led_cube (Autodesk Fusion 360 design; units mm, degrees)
part number: 2026-10-16-17-34-12-747
parameter "cube" = 60 comment "job b4419e02"
parameter "wall" = 2.4 comment "job b4419e02"
parameter "lidT" = 2.4 comment "job b4419e02"
parameter "clr" = 0.2 comment "job b4419e02"
parameter "pcb" = 50 comment "job b4419e02"
parameter "pcbT" = 1.6 comment "job b4419e02"
parameter "pocket" = 50.4 comment "job b4419e02"
parameter "rimW" = 1.8 comment "job b4419e02"
parameter "standoff" = 5 comment "job b4419e02"
parameter "ledH" = 1.6 comment "job b4419e02"
parameter "ledGap" = 15 comment "job b4419e02"
parameter "hookLap" = 0.5 comment "job b4419e02"
parameter "acrT" = 2 comment "job b4419e02"
parameter "acrW" = 56 comment "job b4419e02"
parameter "acrH" = 57 comment "job b4419e02"
parameter "slotW" = 2.3 comment "job b4419e02"
parameter "slotD" = 1.5 comment "job b4419e02"
parameter "win" = 52 comment "job b4419e02"
parameter "cableD" = 5 comment "job b4419e02"
parameter "skirtT" = 1.6 comment "job b4419e02"
parameter "skirtH" = 4 comment "job b4419e02"
parameter "snapL" = 8 comment "job b4419e02"
parameter "snapP" = 0.5 comment "job b4419e02"
parameter "snapH" = 1 comment "job b4419e02"
work_plane "WorkPlane1" AlongDistance 0 ExtraOffset 0
sketch "TubOuter" plane through (0, 0, 0) normal (0, 0, 1) x axis (1, 0, 0)
  line L1 (30, -30) -> (-30, -30)
  line L2 (30, 30) -> (30, -30)
  line L3 (-30, 30) -> (30, 30)
  line L4 (-30, -30) -> (-30, 30)
extrude "Extrude1" new body sketch "TubOuter" along normal blind 57.6 bodies "Tub"
work_plane "WorkPlane2" AlongDistance 2.4 ExtraOffset 0
sketch "Cavity" plane through (0, 0, 2.4) normal (0, 0, 1) x axis (1, 0, 0)
  line L1 (27.6, -27.6) -> (-27.6, -27.6)
  line L2 (27.6, 27.6) -> (27.6, -27.6)
  line L3 (-27.6, 27.6) -> (27.6, 27.6)
  line L4 (-27.6, -27.6) -> (-27.6, 27.6)
extrude "Extrude2" cut sketch "Cavity" along normal blind 55.2
work_plane "WorkPlane3" AlongDistance 4 ExtraOffset 0
sketch "FrontWindow" plane through (0, 0, 4) normal (0, 0, 1) x axis (1, 0, 0)
  line L1 (26, -30) -> (-26, -30)
  line L2 (26, -27.6) -> (26, -30)
  line L3 (-26, -27.6) -> (26, -27.6)
  line L4 (-26, -30) -> (-26, -27.6)
extrude "Extrude3" cut sketch "FrontWindow" along normal blind 52
work_plane "WorkPlane4" AlongDistance 0.9 ExtraOffset 0
sketch "DiffuserSlot" plane through (0, 0, 0.9) normal (0, 0, 1) x axis (1, 0, 0)
  line L1 (29.1, -27.6) -> (-29.1, -27.6)
  line L2 (29.1, -25.3) -> (29.1, -27.6)
  line L3 (-29.1, -25.3) -> (29.1, -25.3)
  line L4 (-29.1, -27.6) -> (-29.1, -25.3)
extrude "Extrude4" cut sketch "DiffuserSlot" along normal blind 56.7
sketch "Bulkhead" plane through (0, 0, 2.4) normal (0, 0, 1) x axis (1, 0, 0)
  line L1 (27.6, -2.4) -> (-27.6, -2.4)
  line L2 (27.6, 0) -> (27.6, -2.4)
  line L3 (-27.6, 0) -> (27.6, 0)
  line L4 (-27.6, -2.4) -> (-27.6, 0)
extrude "Extrude5" add sketch "Bulkhead" along normal blind 51
work_plane "WorkPlane5" AlongDistance 6 ExtraOffset 0
sketch "BulkheadCableHole" plane through (0, 0, 6) normal (0, 0, 1) x axis (1, 0, 0)
  line L1 (5, -2.4) -> (-5, -2.4)
  line L2 (5, 0) -> (5, -2.4)
  line L3 (-5, 0) -> (5, 0)
  line L4 (-5, -2.4) -> (-5, 0)
extrude "Extrude6" cut sketch "BulkheadCableHole" along normal blind 6
work_plane "WorkPlane6" AlongDistance 3 ExtraOffset 0
sketch "PocketRim" plane through (0, 0, 3) normal (0, 0, 1) x axis (1, 0, 0)
  line L1 (27, -9) -> (-27, -9)
  line L2 (27, -2.4) -> (27, -9)
  line L3 (-27, -2.4) -> (27, -2.4)
  line L4 (-27, -9) -> (-27, -2.4)
extrude "Extrude7" add sketch "PocketRim" along normal blind 54
work_plane "WorkPlane7" AlongDistance 4.8 ExtraOffset 0
sketch "PocketInner" plane through (0, 0, 4.8) normal (0, 0, 1) x axis (1, 0, 0)
  line L1 (25.2, -9) -> (-25.2, -9)
  line L2 (25.2, -2.4) -> (25.2, -9)
  line L3 (-25.2, -2.4) -> (25.2, -2.4)
  line L4 (-25.2, -9) -> (-25.2, -2.4)
extrude "Extrude8" cut sketch "PocketInner" along normal blind 50.4
work_plane "WorkPlane8" AlongDistance 5 ExtraOffset 0
sketch "Standoff0" plane through (0, 0, 5) normal (0, 0, 1) x axis (1, 0, 0)
  line L1 (-20, -7.4) -> (-25, -7.4)
  line L2 (-20, -2.4) -> (-20, -7.4)
  line L3 (-25, -2.4) -> (-20, -2.4)
  line L4 (-25, -7.4) -> (-25, -2.4)
extrude "Extrude9" add sketch "Standoff0" along normal blind 5
sketch "Standoff1" plane through (0, 0, 5) normal (0, 0, 1) x axis (1, 0, 0)
  line L1 (25, -7.4) -> (20, -7.4)
  line L2 (25, -2.4) -> (25, -7.4)
  line L3 (20, -2.4) -> (25, -2.4)
  line L4 (20, -7.4) -> (20, -2.4)
extrude "Extrude10" add sketch "Standoff1" along normal blind 5
work_plane "WorkPlane9" AlongDistance 50 ExtraOffset 0
sketch "Standoff2" plane through (0, 0, 50) normal (0, 0, 1) x axis (1, 0, 0)
  line L1 (-20, -7.4) -> (-25, -7.4)
  line L2 (-20, -2.4) -> (-20, -7.4)
  line L3 (-25, -2.4) -> (-20, -2.4)
  line L4 (-25, -7.4) -> (-25, -2.4)
extrude "Extrude11" add sketch "Standoff2" along normal blind 5
sketch "Standoff3" plane through (0, 0, 50) normal (0, 0, 1) x axis (1, 0, 0)
  line L1 (25, -7.4) -> (20, -7.4)
  line L2 (25, -2.4) -> (25, -7.4)
  line L3 (20, -2.4) -> (25, -2.4)
  line L4 (20, -7.4) -> (20, -2.4)
extrude "Extrude12" add sketch "Standoff3" along normal blind 5
work_plane "WorkPlane10" AlongDistance 54.5 ExtraOffset 0
sketch "HookTop" plane through (0, 0, 54.5) normal (0, 0, 1) x axis (1, 0, 0)
  line L1 (4, -9.8) -> (-4, -9.8)
  line L2 (4, -9) -> (4, -9.8)
  line L3 (-4, -9) -> (4, -9)
  line L4 (-4, -9.8) -> (-4, -9)
extrude "Extrude13" add sketch "HookTop" along normal blind 2.5
sketch "HookBottom" plane through (0, 0, 3) normal (0, 0, 1) x axis (1, 0, 0)
  line L1 (4, -9.8) -> (-4, -9.8)
  line L2 (4, -9) -> (4, -9.8)
  line L3 (-4, -9) -> (4, -9)
  line L4 (-4, -9.8) -> (-4, -9)
extrude "Extrude14" add sketch "HookBottom" along normal blind 2.5
sketch "HookReliefL" plane through (0, 0, 3) normal (0, 0, 1) x axis (1, 0, 0)
  line L1 (-4, -9) -> (-5, -9)
  line L2 (-4, -2.4) -> (-4, -9)
  line L3 (-5, -2.4) -> (-4, -2.4)
  line L4 (-5, -9) -> (-5, -2.4)
extrude "Extrude15" cut sketch "HookReliefL" along normal blind 1.8
sketch "HookReliefR" plane through (0, 0, 3) normal (0, 0, 1) x axis (1, 0, 0)
  line L1 (5, -9) -> (4, -9)
  line L2 (5, -2.4) -> (5, -9)
  line L3 (4, -2.4) -> (5, -2.4)
  line L4 (4, -9) -> (4, -2.4)
extrude "Extrude16" cut sketch "HookReliefR" along normal blind 1.8
sketch "ReliefPin0" plane through (0, 0, 2.4) normal (0, 0, 1) x axis (1, 0, 0)
  line L1 (-2, 20) -> (-6, 20)
  line L2 (-2, 24) -> (-2, 20)
  line L3 (-6, 24) -> (-2, 24)
  line L4 (-6, 20) -> (-6, 24)
extrude "Extrude17" add sketch "ReliefPin0" along normal blind 6
sketch "ReliefPin1" plane through (0, 0, 2.4) normal (0, 0, 1) x axis (1, 0, 0)
  line L1 (6, 13) -> (2, 13)
  line L2 (6, 17) -> (6, 13)
  line L3 (2, 17) -> (6, 17)
  line L4 (2, 13) -> (2, 17)
extrude "Extrude18" add sketch "ReliefPin1" along normal blind 6
sketch "ReliefPin2" plane through (0, 0, 2.4) normal (0, 0, 1) x axis (1, 0, 0)
  line L1 (-2, 6) -> (-6, 6)
  line L2 (-2, 10) -> (-2, 6)
  line L3 (-6, 10) -> (-2, 10)
  line L4 (-6, 6) -> (-6, 10)
extrude "Extrude19" add sketch "ReliefPin2" along normal blind 6
sketch "CableGrommet" plane through (0, 30, 0) normal (0, 1, 0) x axis (-1, 0, 0)
  line L1 (30, 0) -> (-30, 0)
  line L2 (30, 57.6) -> (30, 0)
  line L3 (-30, 57.6) -> (30, 57.6)
  line L4 (-30, 0) -> (-30, 57.6)
  circle C1 centre (0, 5.9) radius 2.5
extrude "Extrude20" cut sketch "CableGrommet" profile of C1 against normal blind 2.9
work_plane "WorkPlane11" AlongDistance 57.6 ExtraOffset 0
sketch "LidPlate" plane through (0, 0, 57.6) normal (0, 0, 1) x axis (1, 0, 0)
  line L1 (30, -30) -> (-30, -30)
  line L2 (30, 30) -> (30, -30)
  line L3 (-30, 30) -> (30, 30)
  line L4 (-30, -30) -> (-30, 30)
extrude "Extrude21" new body sketch "LidPlate" along normal blind 2.4 bodies "Lid"
work_plane "WorkPlane12" AlongDistance 53.6 ExtraOffset 0
sketch "Skirt" plane through (0, 0, 53.6) normal (0, 0, 1) x axis (1, 0, 0)
  line L1 (27.4, -25.1) -> (-27.4, -25.1)
  line L2 (27.4, 27.4) -> (27.4, -25.1)
  line L3 (-27.4, 27.4) -> (27.4, 27.4)
  line L4 (-27.4, -25.1) -> (-27.4, 27.4)
extrude "Extrude22" add sketch "Skirt" along normal blind 4
sketch "SkirtInner" plane through (0, 0, 53.6) normal (0, 0, 1) x axis (1, 0, 0)
  line L1 (25.8, -23.5) -> (-25.8, -23.5)
  line L2 (25.8, 25.8) -> (25.8, -23.5)
  line L3 (-25.8, 25.8) -> (25.8, 25.8)
  line L4 (-25.8, -23.5) -> (-25.8, 25.8)
extrude "Extrude23" cut sketch "SkirtInner" along normal blind 4
sketch "SkirtNotch" plane through (0, 0, 53.6) normal (0, 0, 1) x axis (1, 0, 0)
  line L1 (27.5, -9.4) -> (-27.5, -9.4)
  line L2 (27.5, -2) -> (27.5, -9.4)
  line L3 (-27.5, -2) -> (27.5, -2)
  line L4 (-27.5, -9.4) -> (-27.5, -2)
extrude "Extrude24" cut sketch "SkirtNotch" along normal blind 4
sketch "LidDiffuserGroove" plane through (0, 0, 57.6) normal (0, 0, 1) x axis (1, 0, 0)
  line L1 (29.1, -27.6) -> (-29.1, -27.6)
  line L2 (29.1, -25.3) -> (29.1, -27.6)
  line L3 (-29.1, -25.3) -> (29.1, -25.3)
  line L4 (-29.1, -27.6) -> (-29.1, -25.3)
extrude "Extrude25" cut sketch "LidDiffuserGroove" along normal blind 1.5
work_plane "WorkPlane13" AlongDistance 55.1 ExtraOffset 0
sketch "SnapBumpL" plane through (0, 0, 55.1) normal (0, 0, 1) x axis (1, 0, 0)
  line L1 (-27.4, 8) -> (-27.9, 8)
  line L2 (-27.4, 16) -> (-27.4, 8)
  line L3 (-27.9, 16) -> (-27.4, 16)
  line L4 (-27.9, 8) -> (-27.9, 16)
extrude "Extrude26" add sketch "SnapBumpL" along normal blind 1
work_plane "WorkPlane14" AlongDistance 54.9 ExtraOffset 0
sketch "SnapGrooveL" plane through (0, 0, 54.9) normal (0, 0, 1) x axis (1, 0, 0)
  line L1 (-27.6, 7.8) -> (-28.5, 7.8)
  line L2 (-27.6, 16.2) -> (-27.6, 7.8)
  line L3 (-28.5, 16.2) -> (-27.6, 16.2)
  line L4 (-28.5, 7.8) -> (-28.5, 16.2)
extrude "Extrude27" cut sketch "SnapGrooveL" along normal blind 1.4
sketch "SnapBumpR" plane through (0, 0, 55.1) normal (0, 0, 1) x axis (1, 0, 0)
  line L1 (27.9, 8) -> (27.4, 8)
  line L2 (27.9, 16) -> (27.9, 8)
  line L3 (27.4, 16) -> (27.9, 16)
  line L4 (27.4, 8) -> (27.4, 16)
extrude "Extrude28" add sketch "SnapBumpR" along normal blind 1
sketch "SnapGrooveR" plane through (0, 0, 54.9) normal (0, 0, 1) x axis (1, 0, 0)
  line L1 (28.5, 7.8) -> (27.6, 7.8)
  line L2 (28.5, 16.2) -> (28.5, 7.8)
  line L3 (27.6, 16.2) -> (28.5, 16.2)
  line L4 (27.6, 7.8) -> (27.6, 16.2)
extrude "Extrude29" cut sketch "SnapGrooveR" along normal blind 1.4
sketch "SnapBumpBL" plane through (0, 0, 55.1) normal (0, 0, 1) x axis (1, 0, 0)
  line L1 (-8, 27.4) -> (-16, 27.4)
  line L2 (-8, 27.9) -> (-8, 27.4)
  line L3 (-16, 27.9) -> (-8, 27.9)
  line L4 (-16, 27.4) -> (-16, 27.9)
extrude "Extrude30" add sketch "SnapBumpBL" along normal blind 1
sketch "SnapGrooveBL" plane through (0, 0, 54.9) normal (0, 0, 1) x axis (1, 0, 0)
  line L1 (-7.8, 27.6) -> (-16.2, 27.6)
  line L2 (-7.8, 28.5) -> (-7.8, 27.6)
  line L3 (-16.2, 28.5) -> (-7.8, 28.5)
  line L4 (-16.2, 27.6) -> (-16.2, 28.5)
extrude "Extrude31" cut sketch "SnapGrooveBL" along normal blind 1.4
sketch "SnapBumpBR" plane through (0, 0, 55.1) normal (0, 0, 1) x axis (1, 0, 0)
  line L1 (16, 27.4) -> (8, 27.4)
  line L2 (16, 27.9) -> (16, 27.4)
  line L3 (8, 27.9) -> (16, 27.9)
  line L4 (8, 27.4) -> (8, 27.9)
extrude "Extrude32" add sketch "SnapBumpBR" along normal blind 1
sketch "SnapGrooveBR" plane through (0, 0, 54.9) normal (0, 0, 1) x axis (1, 0, 0)
  line L1 (16.2, 27.6) -> (7.8, 27.6)
  line L2 (16.2, 28.5) -> (16.2, 27.6)
  line L3 (7.8, 28.5) -> (16.2, 28.5)
  line L4 (7.8, 27.6) -> (7.8, 28.5)
extrude "Extrude33" cut sketch "SnapGrooveBR" along normal blind 1.4
work_plane "WorkPlane15" AlongDistance 1.2 ExtraOffset 0
sketch "RefAcrylic" plane through (0, 0, 1.2) normal (0, 0, 1) x axis (1, 0, 0)
  line L1 (28, -27.6) -> (-28, -27.6)
  line L2 (28, -25.6) -> (28, -27.6)
  line L3 (-28, -25.6) -> (28, -25.6)
  line L4 (-28, -27.6) -> (-28, -25.6)
extrude "Extrude34" new body sketch "RefAcrylic" along normal blind 57 bodies "RefAcrylic"
sketch "RefPCB" plane through (0, 0, 5) normal (0, 0, 1) x axis (1, 0, 0)
  line L1 (25, -9) -> (-25, -9)
  line L2 (25, -7.4) -> (25, -9)
  line L3 (-25, -7.4) -> (25, -7.4)
  line L4 (-25, -9) -> (-25, -7.4)
extrude "Extrude35" new body sketch "RefPCB" along normal blind 50 bodies "RefPCB"
work_plane "WorkPlane16" AlongDistance 5.625 ExtraOffset 0
sketch "RefLEDs" plane through (0, 0, 5.625) normal (0, 0, 1) x axis (1, 0, 0)
  line L1 (24.375, -10.6) -> (-24.375, -10.6)
  line L2 (24.375, -9) -> (24.375, -10.6)
  line L3 (-24.375, -9) -> (24.375, -9)
  line L4 (-24.375, -10.6) -> (-24.375, -9)
extrude "Extrude36" new body sketch "RefLEDs" along normal blind 48.75 bodies "RefLEDs"
remove_body "RemoveBody1"
remove_body "RemoveBody2"
remove_body "RemoveBody3"
named bodies: "Tub", "Lid", "RefAcrylic", "RefPCB", "RefLEDs"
